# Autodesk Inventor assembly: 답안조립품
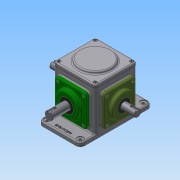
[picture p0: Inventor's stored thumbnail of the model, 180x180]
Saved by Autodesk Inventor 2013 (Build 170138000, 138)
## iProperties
Created: 2019-04
Part Number: 답안조립품
Document SubType Name: Assembly
Designer: Administrator
Mass: 2475.38 g
Surface Area: 2640.96 cm^2
Volume: 832.514 cm^3
Density: 2.97338 g/cm^3
Author: Administrator
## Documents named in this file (16)
- C:\Users\Administrator\Desktop\390407V1019\답안조립품.iam
- C:\Users\Administrator\Desktop\390407V1019\공용부품\본체.ipt
- C:\Users\Administrator\Desktop\390407V1019\공용부품\개스킷.ipt
- C:\Users\Administrator\Desktop\390407V1019\공용부품\메인베벨기어.ipt
- C:\Users\Administrator\Desktop\390407V1019\공용부품\메인축.ipt
- C:\Users\Administrator\Desktop\390407V1019\공용부품\메인커버.ipt
- C:\Users\Administrator\Desktop\390407V1019\공용부품\베어링 6203.ipt
- C:\Users\Administrator\Desktop\390407V1019\공용부품\베어링 6204.ipt
- C:\Users\Administrator\Desktop\390407V1019\공용부품\볼트 M4.ipt
- C:\Users\Administrator\Desktop\390407V1019\공용부품\상부커버.ipt
- C:\Users\Administrator\Desktop\390407V1019\공용부품\서브베벨기어.ipt
- C:\Users\Administrator\Desktop\390407V1019\공용부품\서브축.ipt
- C:\Users\Administrator\Desktop\390407V1019\공용부품\서브커버.ipt
- C:\Users\Administrator\Desktop\390407V1019\공용부품\오일 실 17 32 8.ipt
- C:\Users\Administrator\Desktop\390407V1019\공용부품\오일 실 20 35 8.ipt
- C:\Users\Administrator\Desktop\390407V1019\공용부품\키 4x4.ipt
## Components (1 placed, 1 different names)
1. 개스킷:1
